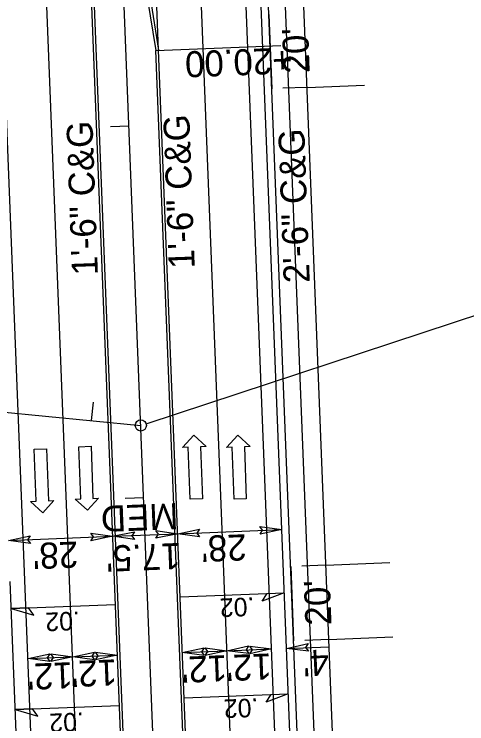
# Model space of a CAD drawing. Extents: x 1627861 to 1629601, y 761281 to 766239.
# Drawn here: x 1628365.8 to 1628487.4, y 764213 to 764403.8 of the extents above; entities that cross this region are included whole.
import ezdxf

# ---------------------------------------------------------------- set-up
doc = ezdxf.new("R2010")
doc.units = 0
for name, color, linetype in [('Exist Property Tie Line Text', 7, 'Continuous'), ('Exist Right of Way Line Leader', 7, 'Continuous'), ('Exist Right of Way Monument Leader', 7, 'Continuous'), ('Exist Right of Way Monument Text', 7, 'Continuous'), ('Exist Utilities Gas Meter CELL', 7, 'Continuous'), ('Exist Utilities Gas Meter Cogo Elevation', 7, 'Continuous'), ('Exist Utilities Gas Meter Cogo Number', 7, 'Continuous'), ('Exist Utilities Gas UG Line', 7, 'Continuous'), ('Exist Utilities Power UG Cable SUE LOS B Cogo Point CELL', 7, 'Continuous'), ('Exist Utilities Water UG Line SUE LOS B Cogo Number', 7, 'Continuous'), ('Exist Utilities Water Valve CELL', 7, 'Continuous'), ('Matchline', 7, 'Continuous'), ('Scratch_Level_0', 7, 'Continuous'), ('Scratch_Level_1', 7, 'Continuous'), ('Typical Terminator CELL', 7, 'Continuous')]:
    doc.layers.add(name, color=color, linetype=linetype)

msp = doc.modelspace()

# ---------------------------------------------------------------- linework, layer by layer
at = {"layer": 'Exist Property Tie Line Text'}
for p, q in [((1628396.65, 764373.68), (1628391.65, 764373.48)), ((1628386.58, 764294.52), (1628387.07, 764299.49)), ((1628400.59, 764273.76), (1628395.59, 764273.56))]:
    msp.add_line(p, q, dxfattribs=at)
at = {"layer": 'Exist Right of Way Line Leader'}
msp.add_line((1628401.25, 764293.68), (1628584.48, 764353.98), dxfattribs=at)
msp.add_circle((1628399.82, 764293.22), 1.5, dxfattribs=at)
at = {"layer": 'Exist Right of Way Monument Leader'}
for p, q in [((1628411.07, 764287.32), (1628414.05, 764290.58)), ((1628414.05, 764290.58), (1628417.36, 764287.54)), ((1628422.87, 764287.31), (1628425.86, 764290.57)), ((1628425.86, 764290.57), (1628429.17, 764287.54)), ((1628371.18, 764286.83), (1628374.48, 764286.95)), ((1628374.48, 764286.95), (1628374.98, 764272.95)), ((1628383.16, 764287.49), (1628386.45, 764287.61)), ((1628383.66, 764273.5), (1628383.16, 764287.49)), ((1628386.45, 764287.61), (1628386.96, 764273.62)), ((1628412.57, 764287.37), (1628411.07, 764287.32)), ((1628413.07, 764273.38), (1628412.57, 764287.37)), ((1628417.36, 764287.54), (1628415.87, 764287.49)), ((1628415.87, 764287.49), (1628416.37, 764273.5)), ((1628424.37, 764287.36), (1628422.87, 764287.31)), ((1628424.87, 764273.37), (1628424.37, 764287.36)), ((1628429.17, 764287.54), (1628427.67, 764287.48)), ((1628427.67, 764287.48), (1628428.17, 764273.49)), ((1628371.68, 764272.84), (1628371.18, 764286.83)), ((1628388.46, 764273.67), (1628385.47, 764270.41)), ((1628386.96, 764273.62), (1628388.46, 764273.67)), ((1628370.18, 764272.78), (1628371.68, 764272.84)), ((1628373.5, 764269.75), (1628370.18, 764272.78)), ((1628376.48, 764273.01), (1628373.5, 764269.75)), ((1628374.98, 764272.95), (1628376.48, 764273.01)), ((1628382.16, 764273.44), (1628383.66, 764273.5)), ((1628385.47, 764270.41), (1628382.16, 764273.44)), ((1628416.37, 764273.5), (1628413.07, 764273.38)), ((1628428.17, 764273.49), (1628424.87, 764273.37))]:
    msp.add_line(p, q, dxfattribs=at)
at = {"layer": 'Exist Right of Way Monument Text'}
for p, q in [((1628451.66, 763911.37), (1628428.17, 764506.9)), ((1628418.64, 763593.94), (1628385.15, 764443.28)), ((1628396.63, 764443.82), (1628404.6, 764394.05)), ((1628438.1, 763544.67), (1628404.6, 764394.05)), ((1628444.52, 764384.09), (1628459.99, 764384.7)), ((1628449.59, 764255.69), (1628466.78, 764256.37)), ((1628367.3, 764185.25), (1628364.7, 764251.23)), ((1628450.38, 764235.71), (1628467.57, 764236.38))]:
    msp.add_line(p, q, dxfattribs=at)
at = {"layer": 'Exist Utilities Gas Meter CELL'}
for p, q in [((1628486.22, 762102.11), (1628373.12, 764970.45)), ((1628317.26, 764301.31), (1628399.82, 764293.22))]:
    msp.add_line(p, q, dxfattribs=at)
at = {"layer": 'Exist Utilities Gas Meter Cogo Elevation'}
msp.add_line((1628453.66, 763911.45), (1628430.17, 764506.97), dxfattribs=at)
at = {"layer": 'Exist Utilities Gas Meter Cogo Number'}
for points in [[(1628431.83, 764266.04), (1628437.7, 764265.21), (1628431.86, 764263.99), (1628432.57, 764265.06)], [(1628386.36, 764264.25), (1628392.24, 764263.42), (1628386.39, 764262.2), (1628387.11, 764263.26)], [(1628398.12, 764262.59), (1628392.24, 764263.42), (1628398.09, 764264.64), (1628397.37, 764263.57)], [(1628403.85, 764264.94), (1628409.73, 764264.11), (1628403.88, 764262.89), (1628404.59, 764263.95)], [(1628415.6, 764263.28), (1628409.73, 764264.11), (1628415.57, 764265.32), (1628414.86, 764264.26)], [(1628370.14, 764261.48), (1628364.26, 764262.31), (1628370.11, 764263.53), (1628369.39, 764262.47)], [(1628416.87, 764231.42), (1628410.98, 764232.19), (1628416.82, 764233.46), (1628416.11, 764232.39)], [(1628428.86, 764231.89), (1628422.97, 764232.66), (1628428.81, 764233.94), (1628428.11, 764232.87)], [(1628429.08, 764233.91), (1628434.97, 764233.14), (1628429.13, 764231.87), (1628429.83, 764232.94)], [(1628444.85, 764232.52), (1628438.96, 764233.3), (1628444.8, 764234.57), (1628444.09, 764233.5)], [(1628375.4, 764229.78), (1628369.52, 764230.56), (1628375.35, 764231.83), (1628374.65, 764230.76)], [(1628375.62, 764231.81), (1628381.51, 764231.03), (1628375.67, 764229.76), (1628376.38, 764230.83)], [(1628387.39, 764230.25), (1628381.51, 764231.03), (1628387.34, 764232.3), (1628386.64, 764231.23)], [(1628387.61, 764232.28), (1628393.5, 764231.5), (1628387.66, 764230.23), (1628388.37, 764231.3)], [(1628417.09, 764233.44), (1628422.97, 764232.66), (1628417.14, 764231.39), (1628417.84, 764232.46)]]:
    msp.add_lwpolyline(points, close=True, dxfattribs=at)
at = {"layer": 'Exist Utilities Gas UG Line'}
for p, q in [((1628474.17, 763238.85), (1628412.82, 764794.64)), ((1628420.44, 763243.74), (1628359.36, 764792.53)), ((1628462.18, 763238.38), (1628400.83, 764794.17)), ((1628408.48, 763242.45), (1628347.37, 764792.06)), ((1628404.6, 764394.05), (1628400.66, 764493.93))]:
    msp.add_line(p, q, dxfattribs=at)
at = {"layer": 'Exist Utilities Water UG Line SUE LOS B Cogo Number'}
for p, q in [((1628410.39, 764247.13), (1628438.37, 764248.23)), ((1628364.98, 764243.99), (1628392.96, 764245.1)), ((1628411.46, 764220), (1628439.44, 764221.1)), ((1628366.05, 764216.86), (1628394.03, 764217.96))]:
    msp.add_line(p, q, dxfattribs=at)
at = {"layer": 'Exist Utilities Water Valve CELL'}
for p, q in [((1628463.98, 763890.82), (1628438.75, 764530.5)), ((1628434.01, 764523.77), (1628458.75, 763896.41))]:
    msp.add_line(p, q, dxfattribs=at)
at = {"layer": 'Matchline'}
for p, q in [((1628419.39, 763593.97), (1628385.9, 764443.31)), ((1628395.89, 764443.7), (1628403.85, 764393.98)), ((1628437.35, 763544.64), (1628403.85, 764393.98))]:
    msp.add_line(p, q, dxfattribs=at)
at = {"layer": 'Scratch_Level_0'}
for p, q in [((1628434.24, 764403.7), (1628435.03, 764383.71)), ((1628403.85, 764393.98), (1628437.46, 764395.3)), ((1628392.24, 764263.42), (1628409.73, 764264.11)), ((1628409.73, 764264.11), (1628437.7, 764265.21)), ((1628364.26, 764262.31), (1628392.24, 764263.42)), ((1628440.1, 764255.31), (1628440.88, 764235.33)), ((1628438.96, 764233.3), (1628450.36, 764233.74)), ((1628410.98, 764232.19), (1628422.97, 764232.66)), ((1628422.97, 764232.66), (1628434.97, 764233.14)), ((1628369.52, 764230.56), (1628381.51, 764231.03)), ((1628381.51, 764231.03), (1628393.5, 764231.5))]:
    msp.add_line(p, q, dxfattribs=at)
at = {"layer": 'Scratch_Level_1'}
for p, q in [((1628444.52, 764384.09), (1628438.03, 764383.83)), ((1628449.59, 764255.69), (1628443.09, 764255.43)), ((1628450.38, 764235.71), (1628443.88, 764235.45))]:
    msp.add_line(p, q, dxfattribs=at)
at = {"layer": 'Typical Terminator CELL'}
for points in [[(1628438.37, 764248.23), (1628432.46, 764246), (1628433.75, 764248.05)], [(1628364.98, 764243.99), (1628371.06, 764242.23), (1628369.6, 764244.17)], [(1628439.44, 764221.1), (1628433.53, 764218.87), (1628434.82, 764220.92)], [(1628366.05, 764216.86), (1628372.13, 764215.1), (1628370.67, 764217.04)]]:
    msp.add_lwpolyline(points, close=True, dxfattribs=at)

# ---------------------------------------------------------------- texts
at = {"layer": 'Exist Utilities Power UG Cable SUE LOS B Cogo Point CELL'}
for s, rotation, p in [('MED', 182.2582, (1628409.75, 764272.36)), ("28'", 182.2582, (1628428.11, 764263.99)), ("28'", 182.2582, (1628382.84, 764262.04)), ("17.5'", 182.2582, (1628410.35, 764261.65)), ("12'", 182.2582, (1628434.84, 764231.96)), ("4'", 182.7862, (1628450.22, 764233.07)), ("12'", 182.2582, (1628393.27, 764230.36)), ("12'", 182.2582, (1628422.9, 764231.5)), ("12'", 182.2582, (1628381.41, 764229.61))]:
    msp.add_text(s, height=7, rotation=rotation, dxfattribs=at).set_placement(p)
at = {"layer": 'Exist Utilities Water UG Line SUE LOS B Cogo Number'}
for p in [(1628430.26, 764247.04), (1628383.35, 764243.23), (1628431.33, 764219.9), (1628384.42, 764216.09)]:
    msp.add_text('.02', height=5, rotation=182.2582, dxfattribs=at).set_placement(p)
at = {"layer": 'Scratch_Level_0'}
for s, rotation, p in [("20'", 92.2582, (1628445.24, 764387.98)), ('+20.00', 182.2582, (1628440.44, 764394.87)), ('1\'-6" C&G', 92.0586, (1628414.33, 764335.45)), ('1\'-6" C&G', 92.0586, (1628388.3, 764333.7)), ('2\'-6" C&G', 92.0586, (1628445.24, 764331.62)), ("20'", 92.2582, (1628451.09, 764239.6))]:
    msp.add_text(s, height=7, rotation=rotation, dxfattribs=at).set_placement(p)

doc.saveas('drawing.dxf')
